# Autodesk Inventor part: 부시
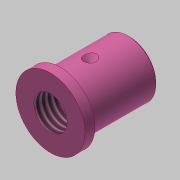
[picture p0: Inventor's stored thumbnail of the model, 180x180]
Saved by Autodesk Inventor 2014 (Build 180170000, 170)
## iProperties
Created: 2019-04
Part Number: 부시
Material: 강철, 연강
Document SubType Name: Modeling
Designer: mduedu
Density: 1 g/cm^3
Appearance: 분홍색
Author: mduedu
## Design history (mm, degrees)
sketch "스케치1"
  geometry: L1 (0, 0)-(3, 0); L2 (3, 0)-(3, 10.5); L3 (3, 10.5)-(0, 10.5); L4 (0, 10.5)-(0, 0); L5 (3, 0)-(24, 0); L6 (24, 0)-(24, 8.5); L7 (24, 8.5)-(3, 8.5); L8 (3, 8.5)-(3, 0)
  constraints: 16 end point, 4 parallel, 2 horizontal, 2 perpendicular
  dimensions: "d0" = 3 distance of L2.end L3.end; "d2" = 24 distance between parallel lines of L6 L4; "d3" = 17 diameter of L7 L5; "d4" = 21 diameter of L3 L1
revolve "회전1" sketch "스케치1" stored, may be unused: angle "d5" = 90 deg
sketch "스케치2"
  geometry: L1 (3, 8.5)-(24, 8.5) reference; L2 (12, 8.5)-(12, 6.5); L3 (12, 6.5)-(14, 8.5); L4 (0, -10.5)-(0, 10.5) reference; 1 further point
  constraints: 4 end point, 2 point on line, 1 perpendicular
  dimensions: "d6" = 12 distance from line of L2.start L4; "d7" = 2 distance of L2.start L3.end; "d8" = 45 deg angle of L3 L2
revolve "회전2" sketch "스케치2" stored, may be unused: angle "d9" = 90 deg
hole "구멍1" diameter "d12" = 10.106; stored, may be unused: countersink angle "d16" = 90 deg, drill point angle "d18" = 118 deg; dims "d10" = 10, "d11" = 10, "d13" = 39, "d14" = 4, "d15" = 2, "d17" = 8
chamfer "모따기1" distance "d19" = 0.5; stored, may be unused: second distance "d20" = 2, angle "d21" = 45 deg
node "작업점1"
  node "작업 평면1"
  node "작업축1"
node "솔리드1"
